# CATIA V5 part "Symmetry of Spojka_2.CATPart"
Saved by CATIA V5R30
Part number: Symmetry of Spojka_2
Bounding box of the stored display mesh (mm): x -8.66 to 8.66, y -7.5 to 7.5, z -9 to 17
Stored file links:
  E:\Bakalarka\Model\Forma_v7\Symmetry of Spojka_2.CATPart
  E:\Bakalarka\Model\Forma_v7\Spojka_1.CATPart
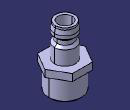
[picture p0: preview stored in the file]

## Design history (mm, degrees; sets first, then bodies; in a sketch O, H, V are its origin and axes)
Body1 (main body)
  Body2 "Body from original PartBody"
    Solid1: linked copy from another document
  Assemble1: tool Body2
